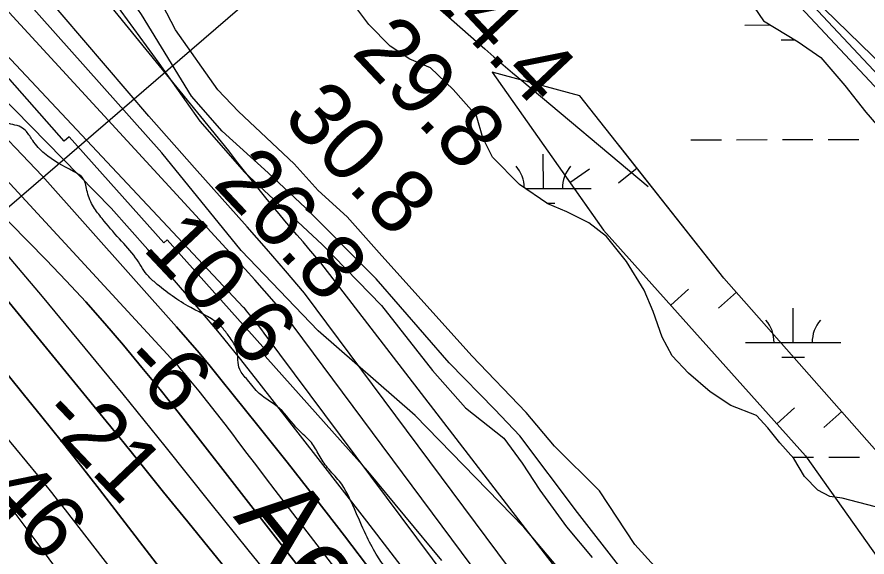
# Model space of a CAD drawing. Extents: x 3329332 to 3367211, y 631066 to 656469.
# Drawn here: x 3350592 to 3351483, y 641695 to 642260 of the extents above; entities that cross this region are included whole.
import ezdxf

# ---------------------------------------------------------------- set-up
doc = ezdxf.new("R2010")
doc.units = 0
for name, color, linetype in [('V-BORW-LINE', 7, 'Continuous'), ('V-LEVE-TOET', 7, 'Continuous'), ('V-RIVR-EDGE', 7, 'Continuous'), ('V-RIVR-IDEN', 7, 'Continuous'), ('V-RIVR-RANG', 7, 'Continuous'), ('V-ROAD-CNTR', 7, 'Continuous'), ('V-RRAP-FSHR', 7, 'Continuous'), ('V-RRAP-RVMT', 7, 'Continuous'), ('V-SITE-VEGE', 7, 'Continuous'), ('V-TOPO-DPTH', 7, 'Continuous'), ('V-TOPO-MAJR', 7, 'Continuous'), ('V-TOPO-MINR', 7, 'Continuous'), ('V-TOPO-WATR', 7, 'Continuous'), ('V-WETL-SWMP', 7, 'Continuous')]:
    doc.layers.add(name, color=color, linetype=linetype)

msp = doc.modelspace()

# ---------------------------------------------------------------- linework, layer by layer
at = {"layer": 'V-BORW-LINE'}
for p, q in [((3351171.73, 642087.06), (3351192.15, 642101.49)), ((3351242.08, 642101.97), (3351222.48, 642086.45)), ((3351277.37, 641958.56), (3351295.99, 641975.24)), ((3351346.31, 641972.03), (3351327.57, 641955.49)), ((3351388.48, 641834.43), (3351407.11, 641851.1)), ((3351456.53, 641847.1), (3351437.78, 641830.56))]:
    msp.add_line(p, q, dxfattribs=at)
for points in [[(3351664.45, 641726.82), (3351527.49, 641766.66), (3351333.1, 641987.01), (3351182.12, 642177.7), (3351090.14, 642202.47), (3351206.99, 642037.19), (3351418.5, 641800.88), (3351520.5, 641657.01), (3351661.77, 641533.36), (3351705.61, 641574.97), (3351712.02, 641662.49), (3351664.45, 641726.82)], [(3351664.45, 641726.82), (3351527.49, 641766.66), (3351333.1, 641987.01), (3351223.28, 642125.71)], [(3351162.85, 642099.63), (3351206.99, 642037.19), (3351418.5, 641800.88), (3351520.5, 641657.01), (3351555.47, 641626.41)]]:
    msp.add_lwpolyline(points, dxfattribs=at)
at = {"layer": 'V-LEVE-TOET'}
msp.add_lwpolyline([(3351869.5, 641779.71), (3351836.36, 641829.54), (3351775.74, 641906.56), (3351700.44, 641988.33), (3351631.3, 642065.42), (3351583.68, 642120.69), (3351514.52, 642194.68), (3351412.25, 642294.43), (3351245.48, 642471.24), (3351150.2, 642573.27), (3351081.79, 642644.93), (3351011.11, 642722.8), (3350880.48, 642863.76), (3350771.28, 642968.21), (3350691.29, 643043.82), (3350616.62, 643103.91), (3350554.27, 643155.41), (3350394.15, 643284.19), (3350311.82, 643355.94), (3350203.23, 643437.16), (3350110.12, 643516.73), (3349979.17, 643610.49), (3349872.15, 643694.02)], dxfattribs=at)
at = {"layer": 'V-RIVR-EDGE'}
msp.add_spline([(3351880.42, 640440.17), (3351876.56, 640444.83), (3351875.03, 640453.75), (3351871.17, 640463.46), (3351865.76, 640470.06), (3351847.23, 640503.46), (3351818.65, 640553.56), (3351810.16, 640569.09), (3351795.85, 640585.8), (3351792.76, 640587.75), (3351786.18, 640593.97), (3351758.32, 640620.8), (3351741.3, 640637.51), (3351732.8, 640648.78), (3351730.49, 640655.38), (3351728.17, 640658.88), (3351720.05, 640667.43), (3351711.55, 640681.02), (3351709.62, 640686.46), (3351709.64, 640692.27), (3351709.27, 640701.97), (3351709.29, 640708.17), (3351711.63, 640715.54), (3351715.92, 640722.89), (3351717.5, 640736.07), (3351718.73, 640762.05), (3351717.22, 640778.35), (3351714.53, 640790.37), (3351713.37, 640790.76), (3351699.41, 640791.96), (3351689.73, 640796.25), (3351681.22, 640805.97), (3351671.17, 640818.02), (3351661.91, 640838.2), (3351651.08, 640851.42), (3351642.96, 640859.58), (3351631.34, 640865.04), (3351621.66, 640871.65), (3351610.83, 640881.38), (3351596.9, 640895.37), (3351584.51, 640905.1), (3351577.55, 640911.71), (3351552.78, 640932.32), (3351530.73, 640953.71), (3351519.12, 640964.21), (3351513.32, 640971.98), (3351507.16, 640987.12), (3351502.9, 640991), (3351492.83, 640996.85), (3351483.55, 641008.11), (3351471.59, 641031.02), (3351466.18, 641038.02), (3351459.21, 641043.85), (3351454.56, 641046.97), (3351449.54, 641056.29), (3351444.54, 641069.48), (3351431.43, 641103.26), (3351426.44, 641123.05), (3351423.74, 641129.26), (3351417.17, 641135.48), (3351410.99, 641147.13), (3351408.29, 641152.56), (3351407.13, 641154.12), (3351401.31, 641154.13), (3351396.67, 641158.8), (3351396.29, 641162.29), (3351398.23, 641164.61), (3351403.29, 641168.48), (3351403.3, 641173.52), (3351399.46, 641188.65), (3351394.81, 641192.15), (3351390.17, 641195.65), (3351385.92, 641202.65), (3351374.34, 641223.62), (3351352.32, 641258.18), (3351324.49, 641295.48), (3351308.25, 641315.3), (3351293.94, 641329.3), (3351280.79, 641344.84), (3351262.62, 641366.99), (3351248.71, 641387.97), (3351231.7, 641409.34), (3351211.2, 641433.04), (3351185.66, 641452.89), (3351174.05, 641464.94), (3351148.52, 641492.15), (3351129.58, 641514.3), (3351119.52, 641526.73), (3351108.7, 641542.27), (3351088.97, 641561.32), (3351069.24, 641578.05), (3351042.55, 641607.59), (3351001.95, 641654.61), (3350991.13, 641669.76), (3350979.14, 641682.98), (3350968.7, 641697.74), (3350957.9, 641718.32), (3350945.94, 641745.11), (3350930.11, 641774.23), (3350917.74, 641788.22), (3350908.85, 641801.43), (3350900.74, 641814.64), (3350886.81, 641828.24), (3350867.48, 641850.4), (3350846.19, 641865.96), (3350833.81, 641880.34), (3350825.7, 641891.22), (3350823.78, 641901.31), (3350821.87, 641913.33), (3350814.53, 641925.76), (3350807.19, 641935.09), (3350774.28, 641956.11), (3350737.11, 641982.18), (3350728.22, 641990.74), (3350716.62, 642008.22), (3350699.61, 642028.04), (3350681.44, 642049.41), (3350672.55, 642061.45), (3350665.99, 642076.98), (3350661.76, 642090.95), (3350651.31, 642098.74), (3350621.11, 642117.43), (3350608.73, 642131.03), (3350602.16, 642140.35), (3350596.36, 642145.02), (3350579.69, 642150.49), (3350575.44, 642153.6), (3350553.39, 642176.15), (3350549.13, 642181.2), (3350546.44, 642189.35), (3350542.19, 642195.18), (3350532.13, 642204.9), (3350519.75, 642218.89), (3350511.24, 642226.28), (3350489.16, 642235.64), (3350466.31, 642247.72), (3350456.25, 642257.05), (3350446.2, 642269.49), (3350443.51, 642279.19), (3350448.18, 642287.71), (3350448.6, 642298.96), (3350443.19, 642308.28), (3350431.97, 642318.77), (3350419.19, 642325.4), (3350405.63, 642329.7), (3350394, 642331.67), (3350385.08, 642332.08), (3350382.37, 642334.8), (3350380.44, 642339.46), (3350380.07, 642346.82), (3350385.13, 642354.57), (3350386.7, 642361.93), (3350384.01, 642369.31), (3350373.59, 642391.44), (3350360.43, 642400.39), (3350342.6, 642404.7), (3350325.92, 642404.74), (3350320.1, 642403.2), (3350313.9, 642402.44), (3350303.83, 642408.67), (3350298.79, 642411.79), (3350296.48, 642416.84), (3350298.44, 642426.14), (3350307.02, 642442.79), (3350316.75, 642460.61), (3350320.25, 642463.7), (3350322.2, 642467.19), (3350321.45, 642477.27), (3350312.94, 642488.15), (3350302.1, 642494.38), (3350278.07, 642501.03), (3350262.19, 642505.73), (3350248.64, 642515.46), (3350230.85, 642536.44), (3350216.17, 642559.36)], degree=3, dxfattribs=at)
at = {"layer": 'V-RIVR-RANG'}
msp.add_line((3351219.96, 642609.71), (3350208.55, 641738.34), dxfattribs=at)
at = {"layer": 'V-ROAD-CNTR'}
msp.add_lwpolyline([(3351492.65, 641335.56), (3351434.25, 641415.79), (3351366.18, 641502.05), (3351179.75, 641741.33), (3351119.1, 641821.57), (3351093.17, 641849.35), (3351045, 641898.18), (3350968.73, 641985.99), (3350894.62, 642060.35), (3350855.32, 642097.18), (3350807.11, 642140.78), (3350775.27, 642177.55), (3350722.86, 642262.97), (3350691.83, 642307.94), (3350641.54, 642374.69), (3350530.63, 642526.9), (3350449.36, 642647.58)], dxfattribs=at)
at = {"layer": 'V-RRAP-FSHR'}
for points in [[(3349424.89, 643987.28), (3349682.59, 643818.4), (3349816.36, 643731.08), (3349921.13, 643649.09), (3350310.29, 643344.41), (3350572.53, 643138.1), (3350702.97, 643034.56), (3350964.76, 642768.6), (3351214.46, 642498.16), (3351553.24, 642137.11), (3351764.26, 641907.98), (3351860.38, 641782.87)], [(3350010.18, 643579.37), (3350310.29, 643344.41), (3350572.53, 643138.1), (3350702.97, 643034.56), (3350964.76, 642768.6), (3351214.46, 642498.16), (3351553.24, 642137.11), (3351764.26, 641907.98), (3351860.38, 641782.87)]]:
    msp.add_lwpolyline(points, dxfattribs=at)
at = {"layer": 'V-RRAP-RVMT'}
for p, q in [((3350641.72, 642130.46), (3350551.47, 642232.21)), ((3350646.87, 642134.79), (3350641.72, 642130.46)), ((3350746.08, 642023.85), (3350646.87, 642134.79)), ((3350749.63, 642027.1), (3350746.08, 642023.85)), ((3350855.73, 641908.46), (3350749.63, 642027.1)), ((3350852.48, 641905.03), (3350855.73, 641908.46)), ((3350959.88, 641784.68), (3350852.48, 641905.03)), ((3351037.43, 641691), (3350959.88, 641784.68))]:
    msp.add_line(p, q, dxfattribs=at)
at = {"layer": 'V-SITE-VEGE'}
for points in [[(3349759.01, 643737.34), (3349909.95, 643649.62), (3350094.98, 643498.56), (3350245.93, 643386.48), (3350426.09, 643245.17), (3350645.2, 643050.25), (3350898.4, 642801.73), (3351258.72, 642436.26), (3351692.08, 641973.33)], [(3351311.6, 641628.5), (3351239.77, 641708.06), (3351202.84, 641764.26), (3351155.41, 641810.84), (3351125.81, 641846.1), (3351068.76, 641905.42), (3350971.75, 642013.5), (3350938.43, 642051.02), (3350908.03, 642078.83), (3350882.85, 642106.6), (3350824.28, 642161.45), (3350802.8, 642183.98), (3350758.46, 642246.94), (3350735.62, 642291.11), (3350687.58, 642357.83), (3350663.13, 642383.36), (3350637.98, 642415.61), (3350602.49, 642463.59), (3350516.78, 642587.26)], [(3350517.78, 642514.15), (3350641.26, 642348.45), (3350741.06, 642212), (3350783.93, 642151.28), (3350830.57, 642098), (3350912.13, 642022.1), (3350974.37, 641958.27), (3351027.62, 641890.03), (3351062.43, 641851), (3351102.5, 641819.4), (3351121.72, 641793.16), (3351140.18, 641764.68), (3351168.28, 641726.45), (3351194.92, 641694.19)], [(3351196.78, 641638.97), (3351123.51, 641726), (3351009.4, 641843.15), (3350907.79, 641931.86), (3350827.04, 642015.96), (3350744.16, 642117.97), (3350601.25, 642278.58), (3350493.19, 642406.88)]]:
    msp.add_lwpolyline(points, dxfattribs=at)
at = {"layer": 'V-TOPO-DPTH'}
for points in [[(3349352.91, 643048.8), (3350048.09, 642577.87), (3350074.83, 642556.17), (3350100.96, 642533.79), (3350126.19, 642510.39), (3350150.8, 642486.31), (3350622.83, 642005.88), (3350643.71, 641984.13), (3350664.24, 641962.05), (3350684.25, 641939.51), (3350703.91, 641916.64), (3350723.18, 641893.44), (3350742.27, 641870.09), (3350761.1, 641846.53), (3350779.75, 641822.83), (3350865.7, 641712.37), (3350927.37, 641633.48), (3351113.97, 641398.04), (3351260.01, 641215.87), (3351265.01, 641209.56), (3351269.96, 641203.19)], [(3349352.91, 643048.8), (3350048.09, 642577.87), (3350074.83, 642556.17), (3350100.96, 642533.79), (3350126.19, 642510.39), (3350150.8, 642486.31), (3350622.83, 642005.88), (3350643.71, 641984.13), (3350664.24, 641962.05), (3350684.25, 641939.51), (3350703.91, 641916.64), (3350723.18, 641893.44), (3350742.27, 641870.09), (3350761.1, 641846.53), (3350779.75, 641822.83), (3350865.7, 641712.37), (3350927.37, 641633.48), (3351113.97, 641398.04), (3351260.01, 641215.87), (3351265.01, 641209.56), (3351269.96, 641203.19)], [(3351189.47, 641201.7), (3350850.61, 641634.21), (3350824.56, 641666.49), (3350798.35, 641698.65), (3350771.25, 641731.66), (3350758.5, 641747.24), (3350745.78, 641762.84), (3350733.12, 641778.49), (3350720.49, 641794.16), (3350704.58, 641813.94), (3350699.92, 641819.73), (3350695.24, 641825.51), (3350690.55, 641831.28), (3350685.84, 641837.03), (3350527.64, 642030.05), (3350457.08, 642114.01), (3350385.18, 642196.79), (3350311.27, 642277.77), (3350236.02, 642357.56), (3350112.21, 642485.67), (3350097.57, 642500.19), (3350082.54, 642514.28), (3350066.94, 642527.72), (3349333.19, 643026.35)], [(3349333.19, 643026.35), (3350066.94, 642527.72), (3350082.54, 642514.28), (3350097.57, 642500.19), (3350112.21, 642485.67), (3350236.02, 642357.56), (3350311.27, 642277.77), (3350385.18, 642196.79), (3350457.08, 642114.01), (3350527.64, 642030.05), (3350685.84, 641837.03), (3350690.55, 641831.28), (3350695.24, 641825.51), (3350699.92, 641819.73), (3350704.58, 641813.94), (3350720.49, 641794.16), (3350733.12, 641778.49), (3350745.78, 641762.84), (3350758.5, 641747.24), (3350771.25, 641731.66), (3350798.35, 641698.65), (3350824.56, 641666.49), (3350850.61, 641634.21), (3351189.47, 641201.7)], [(3351398.1, 641191.14), (3351380.09, 641217.36), (3351352.47, 641257.08), (3351348.09, 641263.31), (3351343.67, 641269.51), (3351339.19, 641275.67), (3351334.67, 641281.8), (3351228.86, 641423.64), (3351171.39, 641500.67), (3350851.42, 641929.24), (3350848.91, 641932.62), (3350846.41, 641936), (3350843.65, 641939.65), (3350841.29, 641942.68), (3350838.87, 641945.65), (3350836.4, 641948.59), (3350832.92, 641952.64), (3350832.15, 641953.52), (3350830.59, 641955.26), (3350829.8, 641956.12), (3350204.43, 642622.26)], [(3351116.54, 641196.41), (3351107.5, 641208.34), (3350698.61, 641739.74), (3350678.72, 641765.4), (3350658.7, 641790.96), (3350638.5, 641816.38), (3350618.17, 641841.69), (3350598.67, 641865.81), (3350568.43, 641903.05), (3350538.1, 641940.23), (3350507.63, 641977.29), (3350477.08, 642014.28), (3350069.18, 642490.21), (3350064.23, 642494.86), (3350059.07, 642499.31), (3350053.79, 642503.61), (3350021.84, 642528.51), (3350013.94, 642534.41), (3350005.9, 642540.1), (3349997.63, 642545.46), (3349989.22, 642550.6), (3349980.71, 642555.61), (3349972.22, 642560.65)], [(3349972.22, 642560.65), (3349980.71, 642555.61), (3349989.22, 642550.6), (3349997.63, 642545.46), (3350005.9, 642540.1), (3350013.94, 642534.41), (3350021.84, 642528.51), (3350053.79, 642503.61), (3350059.07, 642499.31), (3350064.23, 642494.86), (3350069.18, 642490.21), (3350477.08, 642014.28), (3350507.63, 641977.29), (3350538.1, 641940.23), (3350568.43, 641903.05), (3350598.67, 641865.81), (3350618.17, 641841.69), (3350638.5, 641816.38), (3350658.7, 641790.96), (3350678.72, 641765.4), (3350698.61, 641739.74), (3351107.5, 641208.34), (3351116.54, 641196.41)], [(3350965.01, 641677.81), (3350935.37, 641716.83), (3350905.49, 641755.65), (3350875.23, 641794.19), (3350844.73, 641832.53), (3350806.02, 641880.73), (3350794.59, 641894.74), (3350783.01, 641908.64), (3350771.22, 641922.35), (3350759.29, 641935.95), (3350618.53, 642093.94), (3350175.6, 642558.71)], [(3350175.6, 642558.71), (3350618.53, 642093.94), (3350759.29, 641935.95), (3350771.22, 641922.35), (3350783.01, 641908.64), (3350794.59, 641894.74), (3350806.02, 641880.73), (3350844.73, 641832.53), (3350875.23, 641794.19), (3350905.49, 641755.65), (3350935.37, 641716.83), (3350965.01, 641677.81)], [(3351055.19, 641194.2), (3351014.96, 641249.5), (3350974.65, 641304.74), (3350934.21, 641359.89), (3350839.75, 641487.65), (3350798.13, 641543.08), (3350756.11, 641598.19), (3350713.81, 641653.1), (3350643.12, 641744.17), (3350635.92, 641753.36), (3350628.67, 641762.5), (3350621.33, 641771.58), (3350613.93, 641780.61), (3350486.88, 641934.27), (3350415.1, 642019.38), (3350342.22, 642103.51), (3350267.7, 642186.2), (3350192.08, 642267.91), (3350054.74, 642413.43), (3350037.06, 642431.29), (3350018.85, 642448.57), (3349999.84, 642464.97), (3349980.31, 642480.78), (3349884.72, 642554.47)], [(3351055.19, 641194.2), (3351014.96, 641249.5), (3350974.65, 641304.74), (3350934.21, 641359.89), (3350839.75, 641487.65), (3350798.13, 641543.08), (3350756.11, 641598.19), (3350713.81, 641653.1), (3350643.12, 641744.17), (3350635.92, 641753.36), (3350628.67, 641762.5), (3350621.33, 641771.58), (3350613.93, 641780.61), (3350486.88, 641934.27), (3350415.1, 642019.38), (3350342.22, 642103.51), (3350267.7, 642186.2), (3350192.08, 642267.91), (3350054.74, 642413.43), (3350037.06, 642431.29), (3350018.85, 642448.57), (3349999.84, 642464.97), (3349980.31, 642480.78), (3349884.72, 642554.47)]]:
    msp.add_lwpolyline(points, dxfattribs=at)
at = {"layer": 'V-TOPO-MAJR'}
for points in [[(3350475.66, 642760.85), (3351082.41, 642227.13), (3351092.04, 642218.71), (3351101.71, 642210.34), (3351111.44, 642202.05), (3351121.21, 642193.8), (3351253.8, 642082.74)], [(3351483.88, 641234.69), (3351470.92, 641255.39), (3351458.39, 641276.35), (3351446.13, 641297.48), (3351432.17, 641322.15), (3351427.01, 641331.02), (3351421.73, 641339.8), (3350910.65, 642003.01), (3350904.47, 642010.38), (3350898.26, 642017.72), (3350891.98, 642025.01), (3350885.67, 642032.27), (3350879.36, 642039.53), (3350873.1, 642046.83), (3350866.9, 642054.19), (3350860.75, 642061.59), (3350853.05, 642070.95), (3350843.15, 642083.11), (3350833.34, 642095.35), (3350823.68, 642107.7), (3350814.11, 642120.12), (3350339.22, 642702.32)], [(3351031.77, 641146.95), (3350699.31, 641592.8), (3350625.85, 641693.02), (3350611.34, 641712.69), (3350596.74, 641732.3), (3350582.03, 641751.82)]]:
    msp.add_lwpolyline(points, dxfattribs=at)
at = {"layer": 'V-TOPO-MINR'}
for points in [[(3351459.7, 641148.58), (3351388.27, 641252.75), (3351376.13, 641270.28), (3351363.88, 641287.72), (3351351.47, 641305.06), (3351338.94, 641322.31), (3350871.7, 641950.51), (3350861.74, 641962.12), (3350851.7, 641973.65), (3350841.53, 641985.07), (3350831.28, 641996.42), (3350404.3, 642460.49), (3350342.05, 642526.19), (3350242.08, 642631.03), (3350229.4, 642643.89), (3350216.44, 642656.46), (3350203.07, 642668.59), (3350189.43, 642680.43), (3349449, 643139.02), (3349438.18, 643146.14), (3349427.82, 643153.94), (3349417.78, 643162.18), (3348731.92, 643884.66)], [(3351269.96, 641203.19), (3351265.01, 641209.56), (3351260.01, 641215.87), (3351113.97, 641398.04), (3350927.37, 641633.48), (3350865.7, 641712.37), (3350779.75, 641822.83), (3350761.1, 641846.53), (3350742.27, 641870.09), (3350723.18, 641893.44), (3350703.91, 641916.64), (3350684.25, 641939.51), (3350664.24, 641962.05), (3350643.71, 641984.13), (3350622.83, 642005.88), (3350150.8, 642486.31), (3350126.19, 642510.39), (3350100.96, 642533.79), (3350074.83, 642556.17), (3350048.09, 642577.87), (3349352.91, 643048.8)], [(3351189.47, 641201.7), (3350850.61, 641634.21), (3350824.56, 641666.49), (3350798.35, 641698.65), (3350771.25, 641731.66), (3350758.5, 641747.24), (3350745.78, 641762.84), (3350733.12, 641778.49), (3350720.49, 641794.16), (3350704.58, 641813.94), (3350699.92, 641819.73), (3350695.24, 641825.51), (3350690.55, 641831.28), (3350685.84, 641837.03), (3350527.64, 642030.05), (3350457.08, 642114.01), (3350385.18, 642196.79), (3350311.27, 642277.77), (3350236.02, 642357.56), (3350112.21, 642485.67), (3350097.57, 642500.19), (3350082.54, 642514.28), (3350066.94, 642527.72), (3349333.19, 643026.35)], [(3351258.18, 641193.5), (3350873.49, 641654.12), (3350834.47, 641702.25), (3350795.69, 641750.57), (3350747.64, 641810.88), (3350733, 641829.14), (3350718.29, 641847.35), (3350703.48, 641865.47), (3350688.59, 641883.54), (3350618.93, 641967.58), (3350568.47, 642027), (3350517.07, 642085.58), (3350464.29, 642142.9), (3350410.57, 642199.39), (3350131.46, 642485.94), (3350111.85, 642505.26), (3350091.74, 642524.02), (3350070.88, 642541.94), (3350049.52, 642559.31), (3349371.33, 643017.74)], [(3351629.34, 640951.72), (3351419.32, 641259.64), (3351402.75, 641283.71), (3351386.06, 641307.68), (3351369.16, 641331.52), (3351352.14, 641355.27), (3351346.46, 641363.11), (3350893.59, 641971.31), (3350873.73, 641994.53), (3350853.67, 642017.56), (3350833.46, 642040.48), (3350778.27, 642102.53), (3350730.54, 642156.54), (3350275.84, 642687.43)], [(3351398.1, 641191.14), (3351380.09, 641217.36), (3351352.47, 641257.08), (3351348.09, 641263.31), (3351343.67, 641269.51), (3351339.19, 641275.67), (3351334.67, 641281.8), (3351228.86, 641423.64), (3351171.39, 641500.67), (3350851.42, 641929.24), (3350848.91, 641932.62), (3350846.41, 641936), (3350843.65, 641939.65), (3350841.29, 641942.68), (3350838.87, 641945.65), (3350836.4, 641948.59), (3350832.92, 641952.64), (3350832.15, 641953.52), (3350830.59, 641955.26), (3350829.8, 641956.12), (3350204.43, 642622.26)], [(3351116.54, 641196.41), (3351107.5, 641208.34), (3350698.61, 641739.74), (3350678.72, 641765.4), (3350658.7, 641790.96), (3350638.5, 641816.38), (3350618.17, 641841.69), (3350598.67, 641865.81), (3350568.43, 641903.05), (3350538.1, 641940.23), (3350507.63, 641977.29), (3350477.08, 642014.28), (3350069.18, 642490.21), (3350064.23, 642494.86), (3350059.07, 642499.31), (3350053.79, 642503.61), (3350021.84, 642528.51), (3350013.94, 642534.41), (3350005.9, 642540.1), (3349997.63, 642545.46), (3349989.22, 642550.6), (3349980.71, 642555.61), (3349972.22, 642560.65)], [(3351295.16, 641201.85), (3351284.55, 641216.35), (3351273.78, 641230.74), (3351262.89, 641245.03), (3351189.63, 641340.08), (3351142.04, 641401.85), (3350999.37, 641587.24), (3350862.95, 641764.69), (3350852.66, 641778.13), (3350842.41, 641791.59), (3350832.2, 641805.1), (3350822.03, 641818.63), (3350819.33, 641822.23), (3350810.46, 641833.92), (3350801.49, 641845.52), (3350792.36, 641857.01), (3350783.13, 641868.41), (3350771.01, 641883.18), (3350767.74, 641887.12), (3350764.42, 641891.01), (3350761.06, 641894.86), (3350757.65, 641898.68), (3350149.19, 642558.38)], [(3351009.94, 641666.17), (3350958.99, 641732.22), (3350907.85, 641798.11), (3350846.04, 641877.36), (3350825.44, 641903.34), (3350804.56, 641929.09), (3350783.26, 641954.49), (3350761.68, 641979.67), (3350729.25, 642016.88), (3350690.84, 642060.11), (3350202.05, 642559.09)], [(3351055.19, 641194.2), (3351014.96, 641249.5), (3350974.65, 641304.74), (3350934.21, 641359.89), (3350839.75, 641487.65), (3350798.13, 641543.08), (3350756.11, 641598.19), (3350713.81, 641653.1), (3350643.12, 641744.17), (3350635.92, 641753.36), (3350628.67, 641762.5), (3350621.33, 641771.58), (3350613.93, 641780.61), (3350486.88, 641934.27), (3350415.1, 642019.38), (3350342.22, 642103.51), (3350267.7, 642186.2), (3350192.08, 642267.91), (3350054.74, 642413.43), (3350037.06, 642431.29), (3350018.85, 642448.57), (3349999.84, 642464.97), (3349980.31, 642480.78), (3349884.72, 642554.47)]]:
    msp.add_lwpolyline(points, dxfattribs=at)
at = {"layer": 'V-TOPO-WATR'}
msp.add_lwpolyline([(3350965.01, 641677.81), (3350935.37, 641716.83), (3350905.49, 641755.65), (3350875.23, 641794.19), (3350844.73, 641832.53), (3350806.02, 641880.73), (3350794.59, 641894.74), (3350783.01, 641908.64), (3350771.22, 641922.35), (3350759.29, 641935.95), (3350618.53, 642093.94), (3350175.6, 642558.71)], dxfattribs=at)
at = {"layer": 'V-WETL-SWMP'}
for p, q in [((3351354.99, 642251.97), (3351381.54, 642252.02)), ((3351393.02, 642236.61), (3351407.14, 642236.64)), ((3351298.37, 642131.8), (3351330.37, 642131.86)), ((3351346.37, 642131.89), (3351378.37, 642131.95)), ((3351394.37, 642131.98), (3351426.37, 642132.04)), ((3351442.37, 642132.07), (3351474.37, 642132.13)), ((3351143.88, 642080.76), (3351143.81, 642116.76)), ((3351124.92, 642080.73), (3351193.88, 642080.86)), ((3351147.39, 642065.34), (3351155.91, 642065.35)), ((3351405.62, 641919.39), (3351405.55, 641955.39)), ((3351355.62, 641919.3), (3351455.62, 641919.49)), ((3351393.65, 641903.94), (3351417.65, 641903.99)), ((3351405.16, 641799.32), (3351427, 641799.36)), ((3351443, 641799.39), (3351475, 641799.45))]:
    msp.add_line(p, q, dxfattribs=at)
for points in [[(3351324.15, 642332.77), (3351333.79, 642323.75), (3351346.42, 642315.46), (3351356.79, 642304.95), (3351362.68, 642292.97), (3351364.77, 642270.57), (3351374.38, 642256.33), (3351410.79, 642234.44), (3351434.56, 642217.87), (3351459.73, 642188.6), (3351481.93, 642160.84), (3351510.81, 642127.07)], [(3351491.85, 641747.4), (3351456.84, 641756.58), (3351444.16, 641758.16), (3351431.52, 641764.96), (3351417.44, 641779.23), (3351406.38, 641797.96), (3351391.56, 641814.48), (3351378.98, 641830.23), (3351367.13, 641842.99), (3351340.34, 641853.62), (3351318.8, 641867.94), (3351295.8, 641887.5), (3351278.75, 641905.52), (3351268.44, 641924.99), (3351258.92, 641951.92), (3351249.37, 641974.36), (3351230.92, 642004.33), (3351210.2, 642030.59), (3351191.64, 642044.89), (3351168.58, 642056.24), (3351148.49, 642064.58), (3351118.78, 642084.93), (3351090.62, 642113.47), (3351080.31, 642133.69), (3351073.75, 642156.86), (3351049.31, 642184.63), (3351025.58, 642207.18), (3351004.01, 642216.28), (3350983.21, 642229.85), (3350960.97, 642252.38), (3350938.79, 642282.38)]]:
    msp.add_lwpolyline(points, dxfattribs=at)
for centre, start, end in [((3351088.63, 642081.13), 0.49812, 40.88014), ((3351199.12, 642081.34), 139.33648, 180.88013), ((3351350.37, 641919.76), 359.33648, 40.88014), ((3351460.86, 641919.97), 139.33648, 180.88013)]:
    msp.add_arc(centre, 35.25, start, end, dxfattribs=at)

# ---------------------------------------------------------------- texts
at = {"layer": 'V-RIVR-IDEN'}
msp.add_text('Aerial ', height=83, rotation=308.76189, dxfattribs=at).set_placement((3350818.1, 641736.98))
at = {"layer": 'V-RIVR-RANG'}
for s, rotation, p in [('24.4', 313.28833, (3351014.41, 642291.24)), ('29.8', 313.28833, (3350941.79, 642222.49)), ('30.8', 313.28833, (3350869.17, 642153.74)), ('26.8', 313.28833, (3350796.55, 642085)), ('10.6', 313.28833, (3350722.66, 642017.59)), ('-6', 313.57372, (3350698.81, 641896.71)), ('-21', 313.57372, (3350613.65, 641841.15)), ('-46', 313.57372, (3350533.58, 641780.23))]:
    msp.add_text(s, height=67, rotation=rotation, dxfattribs=at).set_placement(p)

doc.saveas('drawing.dxf')
